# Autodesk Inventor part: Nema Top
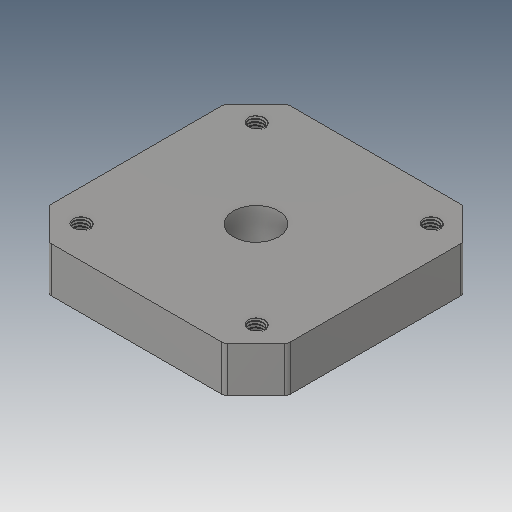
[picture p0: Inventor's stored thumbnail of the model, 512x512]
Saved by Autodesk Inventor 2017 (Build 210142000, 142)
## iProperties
Created: 2018-08
Part Number: Nema Top
Material: Gold
Document SubType Name: Modeling
Designer: JK
Density: 19.3 g/cm^3
Appearance: Metal 1600F Hot
Author: JK
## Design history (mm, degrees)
feature "Nema17 motor"
body "Solid1"
